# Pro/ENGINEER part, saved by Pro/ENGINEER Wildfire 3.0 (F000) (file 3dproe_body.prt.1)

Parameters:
  DESCRIPTION = "SOLID BRASS STOP BODY"
  MODELED_BY = "L. CONARD"
  PTC_COMMON_NAME = "SOLID BRASS STOP BODY"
